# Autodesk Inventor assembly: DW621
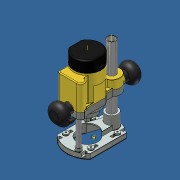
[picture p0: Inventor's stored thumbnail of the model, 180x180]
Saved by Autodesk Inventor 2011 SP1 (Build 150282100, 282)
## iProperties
Created: 2011-02
Part Number: DW621
Document SubType Name: Assembly
Designer: TMT
Description: Oberfrase 230V / 1100W
Vendor: Dewalt
Author: TMT
Comments: Dewalt
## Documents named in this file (12)
- Y:\PROJEKTE\ELLINGHAUS\NKT\fraesvorrichtung_fuer_kabel\INV-Kaufteile\dewalt_DW621.iam
- Y:\PROJEKTE\ELLINGHAUS\NKT\fraesvorrichtung_fuer_kabel\INV-Kaufteile\dewalt_DW621-02.ipt
- Y:\PROJEKTE\ELLINGHAUS\NKT\fraesvorrichtung_fuer_kabel\INV-Kaufteile\dewalt_DW621-01.ipt
- Y:\PROJEKTE\ELLINGHAUS\NKT\fraesvorrichtung_fuer_kabel\INV-Kaufteile\dewalt_DW621-03.ipt
- Y:\PROJEKTE\ELLINGHAUS\NKT\fraesvorrichtung_fuer_kabel\INV-Kaufteile\dewalt_DW621-04.ipt
- Y:\PROJEKTE\ELLINGHAUS\NKT\fraesvorrichtung_fuer_kabel\INV-Kaufteile\dewalt_DW621-05.ipt
- Y:\PROJEKTE\ELLINGHAUS\NKT\fraesvorrichtung_fuer_kabel\INV-Kaufteile\dewalt_DW621-06.ipt
- Y:\PROJEKTE\ELLINGHAUS\NKT\fraesvorrichtung_fuer_kabel\INV-Kaufteile\dewalt_DW621-07.ipt
- Y:\PROJEKTE\ELLINGHAUS\NKT\fraesvorrichtung_fuer_kabel\INV-Kaufteile\dewalt_DW621-08.ipt
- Y:\PROJEKTE\ELLINGHAUS\NKT\fraesvorrichtung_fuer_kabel\INV-Kaufteile\dewalt_DW621-09.ipt
- Y:\PROJEKTE\ELLINGHAUS\NKT\fraesvorrichtung_fuer_kabel\INV-Kaufteile\dewalt_DW621-10.ipt
- Y:\PROJEKTE\ELLINGHAUS\NKT\fraesvorrichtung_fuer_kabel\INV-Kaufteile\dewalt_DW621-11.ipt
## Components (11 placed, 11 different names)
1. dewalt_DW621-02:1 — Passend:1, Fluchtend:1, Passend:2, Einfügen:1, Passend:3
2. dewalt_DW621-01:1 — Einfügen:1, Passend:3, Passend:4, Winkel:1, Einfügen:3, Einfügen:4, Passend:7, Einfügen:5, Winkel:2
3. dewalt_DW621-03:1 — Einfügen:2, Passend:6, Einfügen:4, Passend:7, Passend:8, Einfügen:6, Einfügen:7, Einfügen:8, Einfügen:9
4. dewalt_DW621-04:1 — Einfügen:2, Passend:6
5. dewalt_DW621-05:1 — Einfügen:3
6. dewalt_DW621-06:1 — Einfügen:5
7. dewalt_DW621-07:1 — Passend:8, Drehung/Translation:1
8. dewalt_DW621-08:1 — Einfügen:6, Drehung/Translation:1
9. dewalt_DW621-09:1 — Einfügen:7
10. dewalt_DW621-10:1 — Einfügen:8, Winkel:2
11. dewalt_DW621-11:1 — Einfügen:9
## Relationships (20: Insert 9, Mate 7, Angle 2, Flush 1, RelateRotateTranslate 1)
- Passend:1 [Mate]: dewalt_DW621-02:1
- Fluchtend:1 [Flush]: dewalt_DW621-02:1
- Passend:2 [Mate]: dewalt_DW621-02:1
- Einfügen:1 [Insert]: dewalt_DW621-02:1 ↔ dewalt_DW621-01:1
- Passend:3 [Mate]: dewalt_DW621-02:1 ↔ dewalt_DW621-01:1
- Passend:4 [Mate]: dewalt_DW621-01:1
- Winkel:1 [Angle]: dewalt_DW621-01:1
- Einfügen:2 [Insert]: dewalt_DW621-03:1 ↔ dewalt_DW621-04:1
- Passend:6 [Mate]: dewalt_DW621-03:1 ↔ dewalt_DW621-04:1
- Einfügen:3 [Insert]: dewalt_DW621-01:1 ↔ dewalt_DW621-05:1
- Einfügen:4 [Insert]: dewalt_DW621-01:1 ↔ dewalt_DW621-03:1
- Passend:7 [Mate]: dewalt_DW621-01:1 ↔ dewalt_DW621-03:1
- Einfügen:5 [Insert]: dewalt_DW621-01:1 ↔ dewalt_DW621-06:1
- Passend:8 [Mate]: dewalt_DW621-03:1 ↔ dewalt_DW621-07:1
- Einfügen:6 [Insert]: dewalt_DW621-03:1 ↔ dewalt_DW621-08:1
- Drehung/Translation:1 [RelateRotateTranslate]: dewalt_DW621-07:1 ↔ dewalt_DW621-08:1
- Einfügen:7 [Insert]: dewalt_DW621-03:1 ↔ dewalt_DW621-09:1
- Einfügen:8 [Insert]: dewalt_DW621-03:1 ↔ dewalt_DW621-10:1
- Winkel:2 [Angle]: dewalt_DW621-01:1 ↔ dewalt_DW621-10:1
- Einfügen:9 [Insert]: dewalt_DW621-03:1 ↔ dewalt_DW621-11:1
